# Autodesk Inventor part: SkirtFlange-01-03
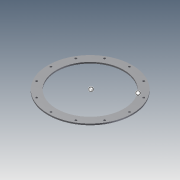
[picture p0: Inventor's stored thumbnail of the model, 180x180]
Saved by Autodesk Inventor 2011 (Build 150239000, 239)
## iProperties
Created: 2010-06
Part Number: SkirtFlange-01-03
Document SubType Name: Modeling
Designer: mklassen
Density: 1 g/cm^3
OD: 36.000 in
THK: 0.500 in
WDT: 3.000 in
BHN: 12.000 ul
BHD: 0.750 in
BCD: 20.000 in
Author: mklassen
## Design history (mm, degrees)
sketch "skSkirtFlange"
  geometry: C1 r 457.2 at (0, 0); C2 r 533.4 at (0, 0); 1 further point
  constraints: 2 centre point, 2 coincident
  dimensions: "d0" = 76.2 radial gap between concentric circles of C2 C1 (derived); "d1" = 914.4 diameter of C1 (derived)
extrude "SkirtFlange" new body sketch "skSkirtFlange" stored distance "d2" = 12.7 (derived); taper "d3" = 0 deg
sketch "skBoltHole"
  geometry: C1 r 457.2 at (0, 0) reference; 2 further points
  constraints: 1 coincident, 1 vertical alignment
  dimensions: "d7" = 508 distance of point (0, 508) point (0, 0) (= BCD)
hole "BoltHole" sketch "skBoltHole" at (0, 508) diameter "d8" = 19.05 (derived); stored, may be unused: countersink angle "d12" = 82 deg, drill point angle "d14" = 118 deg; dims "d9" = 19.05, "d10" = 9.525, "d11" = 6.35, "d13" = 25.4
pattern_circular "BoltCircle" dims angle "d16" = 360 deg
body "Solid1"
other parameters: "BCD" = 508 [user parameter; used in 2 equation terms], "d4" = 0, "d5" = 0, "d6" = 0
